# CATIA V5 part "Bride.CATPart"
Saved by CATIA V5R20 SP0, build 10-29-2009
Part number: Bride
Bounding box of the stored display mesh (mm): x -62 to 4.09, y 24.501 to 52.999, z -18 to -4
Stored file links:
  E:\Boulot\SeaTech\2eme ANNEE\FabricationAdditive\TP_MOSM_CREM\Projet Sauterelle de serrage\CAO Assemblage Sauterelle\Bride.CATPart
  E:\Boulot\SeaTech\2eme ANNEE\FabricationAdditive\TP_MOSM_CREM\Projet Sauterelle de serrage\CAO Assemblage Sauterelle\Sauterelle_horizontale_05120-06.CATPart
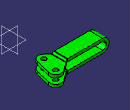
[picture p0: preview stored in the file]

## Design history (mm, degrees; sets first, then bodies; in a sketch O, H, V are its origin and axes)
Body1 (main body)
  Solid1 "05120-06_2": solid without history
